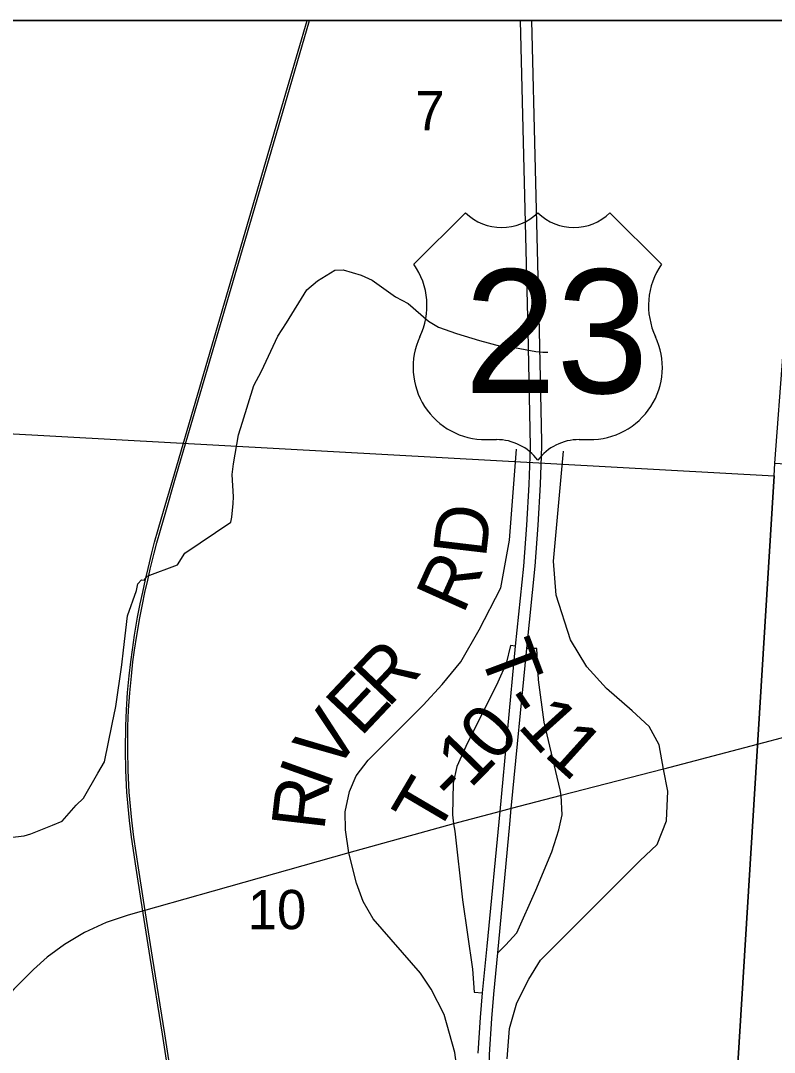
# Model space of a CAD drawing. Extents: x 0 to 34, y 0 to 22.
# Drawn here: x 5.01 to 5.813, y 19.8 to 20.9 of the extents above; entities that cross this region are included whole.
import ezdxf

# ---------------------------------------------------------------- set-up
doc = ezdxf.new("R2010")
doc.units = 0
for name, color, linetype in [('GM_X_Corporation', 7, 'Continuous'), ('GM_X_County_Road', 7, 'Continuous'), ('GM_X_Interchange_Ramps', 7, 'Continuous'), ('GM_X_Minor_River', 7, 'Continuous'), ('GM_X_Rail_Line', 7, 'Continuous'), ('GM_X_Section_Text', 7, 'Continuous'), ('GM_X_State_Route', 7, 'Continuous'), ('GM_X_Township_Road', 7, 'Continuous'), ('GM_X_Township_Road_Text', 7, 'Continuous'), ('GM_X_US_Location', 7, 'Continuous'), ('GM_X_US_Route', 7, 'Continuous'), ('GM_X_US_Shield', 7, 'Continuous'), ('SH_Data', 7, 'Continuous')]:
    doc.layers.add(name, color=color, linetype=linetype)

msp = doc.modelspace()

# ---------------------------------------------------------------- linework, layer by layer
at = {"layer": 'GM_X_Corporation'}
for points in [[(5.849, 20.9), (4.9193, 20.9), (4.8316, 20.6941), (4.8161, 20.4698), (5.8125, 20.4147), (5.8133, 20.4283)], [(4.8161, 20.4698), (5.8125, 20.4147), (5.7537, 19.4608), (5.102, 19.4969), (4.7709, 19.8114)], [(5.8125, 20.4147), (5.8133, 20.4283), (6.802, 20.3679), (6.741, 19.4109), (5.7537, 19.4608)]]:
    msp.add_lwpolyline(points, close=True, dxfattribs=at)
msp.add_lwpolyline([(8.9, 20.9), (4.892, 20.9)], dxfattribs=at)
at = {"layer": 'GM_X_County_Road'}
for points in [[(5.5283, 19.7934), (5.5307, 19.8259), (5.5388, 19.8531), (5.5516, 19.8784), (5.5638, 19.8988), (5.6698, 20.0045), (5.688, 20.022), (5.6979, 20.047), (5.6994, 20.0788), (5.6949, 20.1022)], [(5.4979, 19.4701), (5.5046, 19.5035), (5.5068, 19.5361), (5.5041, 19.5725), (5.4963, 19.6196), (5.4871, 19.6909), (5.4727, 19.8002), (5.4613, 19.8409), (5.4473, 19.8677), (5.4361, 19.8848), (5.3856, 19.9428), (5.3751, 19.9612), (5.3678, 19.9806), (5.3598, 20.0131)]]:
    msp.add_lwpolyline(points, dxfattribs=at)
at = {"layer": 'GM_X_Interchange_Ramps'}
for points in [[(5.5374, 20.2335), (5.5318, 20.2341), (5.5272, 20.2148), (5.5186, 20.1949), (5.4993, 20.1563), (5.486, 20.1304), (5.4747, 20.1052), (5.4707, 20.0872), (5.4703, 20.0537), (5.4712, 20.0441)], [(5.586, 20.074), (5.5847, 20.0801), (5.5677, 20.1524), (5.5618, 20.1975), (5.5598, 20.2308), (5.5492, 20.2309)], [(5.5184, 19.9064), (5.5266, 19.9148), (5.5386, 19.9279), (5.5589, 19.9732), (5.576, 20.0141), (5.5834, 20.0375), (5.5871, 20.0534), (5.586, 20.074)], [(5.4712, 20.0441), (5.4725, 20.0363), (5.4807, 19.9629), (5.4913, 19.8891), (5.4933, 19.8646), (5.5022, 19.8637)]]:
    msp.add_lwpolyline(points, dxfattribs=at)
at = {"layer": 'GM_X_Minor_River'}
msp.add_lwpolyline([(4.9956, 20.0289), (5.0142, 20.0311), (5.0211, 20.0333), (5.0443, 20.0427), (5.0546, 20.0468), (5.0695, 20.0638), (5.0771, 20.0713), (5.0925, 20.0978), (5.0997, 20.1099), (5.1079, 20.1502), (5.1118, 20.1691), (5.1181, 20.2136), (5.12, 20.2291), (5.124, 20.2656), (5.1336, 20.2925), (5.1352, 20.2997), (5.139, 20.3039), (5.1417, 20.3035), (5.1451, 20.308), (5.1775, 20.3199), (5.1851, 20.3324), (5.234, 20.3655), (5.2351, 20.3708), (5.2367, 20.3853), (5.2368, 20.3925), (5.2357, 20.4164), (5.2369, 20.4275), (5.2424, 20.4586), (5.2466, 20.4722), (5.2586, 20.5113), (5.2666, 20.5264), (5.2843, 20.5636), (5.2935, 20.5779), (5.3149, 20.6131), (5.3264, 20.6226), (5.3447, 20.6342), (5.3538, 20.6345), (5.3728, 20.6287), (5.3846, 20.6233), (5.4096, 20.6056), (5.4229, 20.5987), (5.4445, 20.5796), (5.4551, 20.5734), (5.4745, 20.5664), (5.4988, 20.559), (5.5212, 20.5532), (5.536, 20.5516), (5.5588, 20.5472), (5.5664, 20.5468), (5.5718, 20.5467)], dxfattribs=at)
at = {"layer": 'GM_X_Rail_Line'}
for points in [[(5.1731, 19.7437), (5.1614, 19.8198), (5.1484, 19.9015), (5.1388, 19.9622), (5.1334, 19.9967), (5.1284, 20.0296), (5.1263, 20.0475), (5.1248, 20.0625), (5.1235, 20.0776), (5.1224, 20.1008), (5.122, 20.1228), (5.1222, 20.148), (5.1229, 20.1653), (5.1241, 20.1838), (5.1258, 20.2017), (5.1275, 20.2168), (5.1293, 20.2293), (5.1317, 20.2451), (5.1349, 20.2641), (5.1377, 20.2784), (5.1404, 20.2909), (5.1433, 20.3043), (5.1461, 20.3161), (5.1501, 20.3329), (5.153, 20.3441), (5.1569, 20.3576), (5.1625, 20.3772), (5.1723, 20.4108), (5.2867, 20.8021), (5.3154, 20.9)], [(5.1755, 19.744), (5.1638, 19.8202), (5.1507, 19.9018), (5.1412, 19.9625), (5.1358, 19.997), (5.1308, 20.0299), (5.1287, 20.0478), (5.1272, 20.0627), (5.1259, 20.0778), (5.1248, 20.1009), (5.1244, 20.1229), (5.1246, 20.148), (5.1253, 20.1651), (5.1265, 20.1836), (5.1282, 20.2014), (5.1299, 20.2165), (5.1317, 20.229), (5.134, 20.2447), (5.1373, 20.2637), (5.1401, 20.2779), (5.1427, 20.2904), (5.1456, 20.3038), (5.1484, 20.3155), (5.1525, 20.3323), (5.1554, 20.3434), (5.1592, 20.357), (5.1648, 20.3766), (5.1746, 20.4101), (5.289, 20.8015), (5.3179, 20.9)]]:
    msp.add_lwpolyline(points, dxfattribs=at)
at = {"layer": 'GM_X_State_Route'}
for p, q in [((5.6949, 20.1022), (5.586, 20.074)), ((5.3598, 20.0131), (5.2154, 19.9723))]:
    msp.add_line(p, q, dxfattribs=at)
for points in [[(6.482, 20.2837), (6.4584, 20.2857), (6.4209, 20.2864), (6.3958, 20.2857), (6.3728, 20.2847), (6.3346, 20.2765), (6.2919, 20.263), (6.2633, 20.2532), (6.2245, 20.2413), (6.1498, 20.2209), (6.0959, 20.2068), (6.0505, 20.1946), (5.9266, 20.1634), (5.6949, 20.1022)], [(5.586, 20.074), (5.5326, 20.0604), (5.5208, 20.0572), (5.4712, 20.0441), (5.3598, 20.0131)], [(5.2154, 19.9723), (5.1248, 19.9467), (5.1015, 19.9387), (5.0782, 19.9281), (5.0571, 19.9155), (5.0387, 19.9018), (5.0239, 19.8886), (5.0029, 19.8676), (4.9843, 19.8469)]]:
    msp.add_lwpolyline(points, dxfattribs=at)
at = {"layer": 'GM_X_Township_Road'}
for points in [[(5.3598, 20.0131), (5.3563, 20.0375), (5.356, 20.0569), (5.3606, 20.0786), (5.3675, 20.0953), (5.3803, 20.1118), (5.4389, 20.1703), (5.4592, 20.1923), (5.479, 20.2167), (5.4987, 20.2509), (5.5217, 20.2954), (5.5309, 20.3464), (5.5384, 20.4434)], [(5.6949, 20.1022), (5.6903, 20.128), (5.6797, 20.1476), (5.6615, 20.1643), (5.6341, 20.1881), (5.6131, 20.2112), (5.5957, 20.24), (5.5806, 20.2877), (5.5777, 20.3238), (5.5882, 20.4411)]]:
    msp.add_lwpolyline(points, dxfattribs=at)
at = {"layer": 'GM_X_US_Route'}
for p, q in [((5.5586, 20.7418), (5.5546, 20.9)), ((5.5184, 19.9064), (5.5311, 20.0437))]:
    msp.add_line(p, q, dxfattribs=at)
for points in [[(5.5531, 20.4454), (5.5532, 20.4464), (5.5508, 20.5693), (5.5425, 20.9)], [(5.5652, 20.4515), (5.5629, 20.5694), (5.5586, 20.7418)], [(5.5374, 20.2335), (5.5461, 20.3185), (5.5492, 20.3622), (5.5518, 20.4056), (5.5531, 20.4454)], [(5.5492, 20.2309), (5.5581, 20.3186), (5.5613, 20.3623), (5.5639, 20.4057), (5.5653, 20.4465), (5.5652, 20.4515)], [(5.4974, 19.7994), (5.5001, 19.8376), (5.5022, 19.8637), (5.507, 19.9135), (5.5208, 20.0572), (5.5374, 20.2335)], [(5.5311, 20.0437), (5.5326, 20.0604), (5.5492, 20.2309)], [(5.5469, 19.4647), (5.5405, 19.5029), (5.5173, 19.6474), (5.5126, 19.6824), (5.5097, 19.7166), (5.5081, 19.7488), (5.5095, 19.7982), (5.5121, 19.8364), (5.5142, 19.8625), (5.5184, 19.9064)]]:
    msp.add_lwpolyline(points, dxfattribs=at)
at = {"layer": 'GM_X_US_Shield'}
for p, q in [((5.484, 20.6952), (5.4291, 20.6403)), ((5.6928, 20.6403), (5.6378, 20.6952)), ((5.506, 20.4535), (5.517, 20.4535)), ((5.6049, 20.4535), (5.6159, 20.4535))]:
    msp.add_line(p, q, dxfattribs=at)
for centre, radius, start, end in [((5.5225, 20.7344), 0.0549, 225.573, 314.427), ((5.5994, 20.7344), 0.0549, 225.573, 314.427), ((5.3661, 20.5962), 0.0769, 334.5471, 35.0009), ((5.7558, 20.5962), 0.0769, 144.9991, 205.4529), ((5.5051, 20.5304), 0.0769, 154.8319, 270.6383), ((5.6167, 20.5304), 0.0769, 269.3617, 25.1681), ((5.517, 20.3986), 0.0549, 36.8699, 90), ((5.6049, 20.3986), 0.0549, 90, 143.1301)]:
    msp.add_arc(centre, radius, start, end, dxfattribs=at)
at = {"layer": 'SH_Data'}
for p, q in [((2.1, 20.9), (8.9, 20.9)), ((5.484, 20.6952), (5.4291, 20.6403)), ((5.6928, 20.6403), (5.6378, 20.6952)), ((5.506, 20.4535), (5.517, 20.4535)), ((5.6049, 20.4535), (5.6159, 20.4535))]:
    msp.add_line(p, q, dxfattribs=at)
for centre, radius, start, end in [((5.5225, 20.7344), 0.0549, 225.573, 314.427), ((5.5994, 20.7344), 0.0549, 225.573, 314.427), ((5.3661, 20.5962), 0.0769, 334.5471, 35.0009), ((5.7558, 20.5962), 0.0769, 144.9991, 205.4529), ((5.5051, 20.5304), 0.0769, 154.8319, 270.6383), ((5.6167, 20.5304), 0.0769, 269.3617, 25.1681), ((5.517, 20.3986), 0.0549, 36.8699, 90), ((5.6049, 20.3986), 0.0549, 90, 143.1301)]:
    msp.add_arc(centre, radius, start, end, dxfattribs=at)

# ---------------------------------------------------------------- texts
at = {"layer": 'GM_X_Section_Text'}
for s, height, p in [('7', 0.0419, (5.4305, 20.7831)), ('10', 0.04186, (5.2522, 19.9317))]:
    msp.add_text(s, height=height, rotation=0, dxfattribs=at).set_placement(p)
at = {"layer": 'GM_X_Township_Road_Text'}
for s, rotation, p in [('D', 83.2763, (5.5056, 20.3265)), ('R', 65.7954, (5.4815, 20.2661)), ('T', 290.5049, (5.4982, 20.2267)), ('R', 46.4242, (5.4015, 20.1666)), ('E', 46.6821, (5.3724, 20.1357)), ('-', 304.2292, (5.5199, 20.1737)), ('V', 53.5031, (5.3438, 20.0969)), ('0', 48.2751, (5.5154, 20.1077)), ('1', 312.0493, (5.5383, 20.1478)), ('1', 317.9813, (5.5662, 20.1173)), ('1', 45.6675, (5.4891, 20.0806)), ('I', 70.3777, (5.3381, 20.0788)), ('R', 83.4167, (5.3335, 20.0358)), ('T', 59.5162, (5.4525, 20.0299)), ('-', 44.6026, (5.4716, 20.0634))]:
    msp.add_text(s, height=0.0568, rotation=rotation, dxfattribs=at).set_placement(p)
at = {"layer": 'GM_X_US_Location'}
for s in ['0', '/']:
    msp.add_text(s, height=0.000189, dxfattribs=at).set_placement((5.5609, 20.5678))
msp.add_text('23', height=0.000189, rotation=0, dxfattribs=at).set_placement((5.5218, 20.5286))
at = {"layer": 'GM_X_US_Shield'}
msp.add_text('23', height=0.13184, dxfattribs=at).set_placement((5.4827, 20.503))
at = {"layer": 'SH_Data'}
msp.add_text('23', height=0.13184, dxfattribs=at).set_placement((5.4827, 20.503))

doc.saveas('drawing.dxf')
